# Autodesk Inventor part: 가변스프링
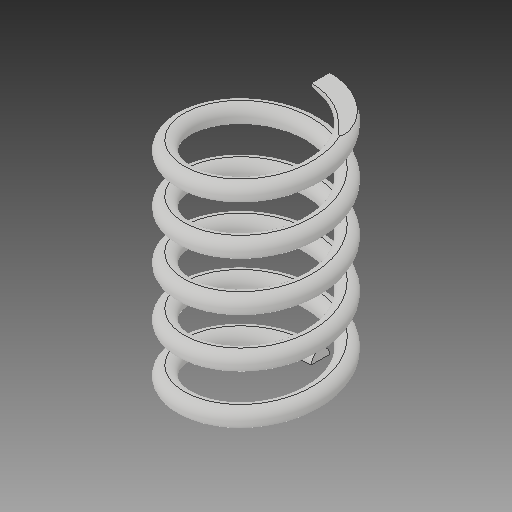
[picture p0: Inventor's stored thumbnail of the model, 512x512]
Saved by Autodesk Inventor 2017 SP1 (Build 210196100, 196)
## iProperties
Part Number: 가변스프링
Material: 일반
Document SubType Name: Modeling
Designer: 00-00
Density: 1 g/cm^3
Appearance: 기본값
Author: 00-00
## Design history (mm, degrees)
sketch "스케치1"
  geometry: L1 (0, 0)-(26.5, 0); L2 (26.5, 0)-(26.5, -7); L3 (26.5, -7)-(0, -7); L4 (0, -7)-(0, 0); C1 r 1 at (0, -7)
  constraints: 8 end point, 2 parallel, 1 centre point, 1 coincident, 1 horizontal, 1 perpendicular
  dimensions: "d0" = 14 diameter of L3 L1; "d1" = 2 diameter of C1; "d2" = 26.5 distance of L1.start L1.end (derived)
feature "코일1" sketch "스케치1" pitch "d3" = 10; turns "d5" = 5; dims "d4" = 26.5 (= d2), "d6" = 0, angle "d7" = 90 deg, angle "d8" = 90 deg, "d9" = 0, "d10" = 0
sketch "스케치2"
  geometry: L1 (-20.079, 26.5)-(20.079, 26.5); L2 (20.079, 26.5)-(20.079, 0); L3 (20.079, 0)-(-20.079, 0); L4 (-20.079, 0)-(-20.079, 26.5); 2 further points
  constraints: 8 end point, 2 parallel, 1 coincident, 1 horizontal, 1 midpoint, 1 perpendicular
  dimensions: "d11" = 40.15822 distance of L1.start L1.end; "d12" = 26.5 distance of L1.end L2.end (= d2)
extrude "돌출1" sketch "스케치2" stored distance "d13" = 63.25; taper "d14" = 0 deg
node "솔리드1"
